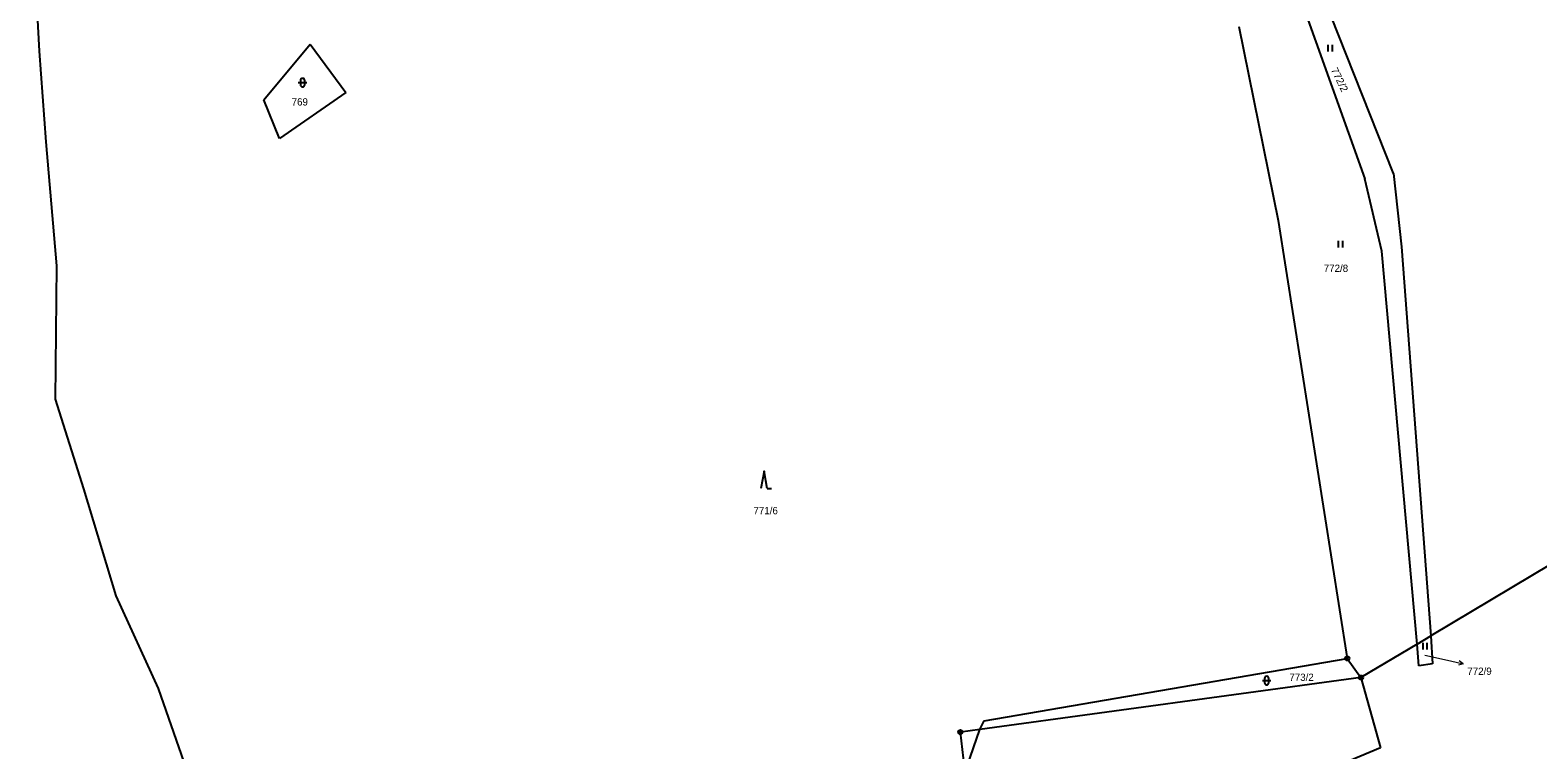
# Model space of a CAD drawing. Extents: x -754970 to -752637, y -970569 to -968179.
# Drawn here: x -754506.1 to -754155, y -970322.9 to -970155.3 of the extents above; entities that cross this region are included whole.
import ezdxf
from ezdxf.enums import TextEntityAlignment as Align

# ---------------------------------------------------------------- set-up
doc = ezdxf.new("R2010")
doc.units = 0
doc.header["$LTSCALE"] = 0.68
for name, color, linetype, lineweight in [('1', 7, 'Continuous', 25), ('3', 7, 'Continuous', 25), ('7', 7, 'Continuous', 13), ('8', 7, 'Continuous', 25)]:
    doc.layers.add(name, color=color, linetype=linetype, lineweight=lineweight)
doc.layers.add('2', color=7, linetype='Continuous')

msp = doc.modelspace()

# ---------------------------------------------------------------- linework, layer by layer
at = {"layer": '1'}
for p, q in [((-754216.79, -970129.79), (-754195.3, -970189.96)), ((-754188.66, -970188.7), (-754212.44, -970128.61)), ((-754224.62, -970154.43), (-754215.47, -970199.68)), ((-754451.69, -970171.53), (-754440.95, -970158.57)), ((-754440.95, -970158.57), (-754432.62, -970169.82)), ((-754502.39, -970181.3), (-754503.93, -970160.19)), ((-754448.06, -970180.57), (-754451.69, -970171.53)), ((-754432.62, -970169.82), (-754448.06, -970180.57)), ((-754499.91, -970210.21), (-754502.39, -970181.3)), ((-754191.35, -970206.76), (-754195.3, -970189.96)), ((-754188.66, -970188.7), (-754186.77, -970205.78)), ((-754215.47, -970199.68), (-754199.39, -970301.65)), ((-754183.14, -970298.3), (-754191.35, -970206.76)), ((-754186.77, -970205.78), (-754179.98, -970296.42)), ((-754500.27, -970241.29), (-754499.91, -970210.21)), ((-754042.77, -970214.3), (-754179.98, -970296.42)), ((-754493.61, -970262.16), (-754500.27, -970241.29)), ((-754486.12, -970287.1), (-754493.61, -970262.16)), ((-754476.28, -970308.62), (-754486.12, -970287.1)), ((-754183.14, -970298.3), (-754196.22, -970306.09)), ((-754183.14, -970298.3), (-754179.98, -970296.42)), ((-754182.71, -970303.39), (-754183.14, -970298.3)), ((-754179.98, -970296.42), (-754179.55, -970302.93)), ((-754283.98, -970316.21), (-754199.39, -970301.65)), ((-754199.39, -970301.65), (-754196.22, -970306.09)), ((-754179.55, -970302.93), (-754182.71, -970303.39)), ((-754468.5, -970330.9), (-754476.28, -970308.62)), ((-754196.22, -970306.09), (-754285, -970318.19)), ((-754196.22, -970306.09), (-754191.69, -970322.5)), ((-754285, -970318.19), (-754283.98, -970316.21)), ((-754285, -970318.19), (-754289.51, -970318.8)), ((-754279.06, -970409.25), (-754289.51, -970318.8)), ((-754287.93, -970326.74), (-754285, -970318.19)), ((-754191.69, -970322.5), (-754258.35, -970350.29))]:
    msp.add_line(p, q, dxfattribs=at)
msp.add_lwpolyline([(-754503.93, -970160.19), (-754504.95, -970141.47), (-754506.14, -970118.68)], dxfattribs=at)
at = {"layer": '3'}
for p, q in [((-754203.851, -970160.26), (-754203.851, -970158.76)), ((-754202.85, -970160.26), (-754202.85, -970158.76)), ((-754443.701, -970167.541), (-754441.699, -970167.541)), ((-754443.201, -970167.041), (-754443.201, -970168.042)), ((-754442.199, -970168.042), (-754442.199, -970167.041)), ((-754201.451, -970205.91), (-754201.451, -970204.41)), ((-754200.45, -970205.91), (-754200.45, -970204.41)), ((-754334.48, -970262.05), (-754333.484, -970262.05)), ((-754181.761, -970299.55), (-754181.761, -970298.05)), ((-754180.76, -970299.55), (-754180.76, -970298.05)), ((-754219.171, -970306.801), (-754217.169, -970306.801)), ((-754218.671, -970306.301), (-754218.671, -970307.302)), ((-754217.669, -970307.302), (-754217.669, -970306.301))]:
    msp.add_line(p, q, dxfattribs=at)
msp.add_lwpolyline([(-754334.48, -970262.05), (-754335.23, -970258.05), (-754335.98, -970262.05)], dxfattribs=at)
for centre, start, end in [((-754442.7, -970167.0409), 0, 180), ((-754442.7, -970168.0409), 180, 359.98789), ((-754218.17, -970306.3009), 0, 180), ((-754218.17, -970307.3009), 180, 359.98789)]:
    msp.add_arc(centre, 0.5, start, end, dxfattribs=at)
at = {"layer": '7'}
msp.add_line((-754172.446, -970302.915), (-754173.309, -970302.202), dxfattribs=at)
msp.add_lwpolyline([(-754181.34, -970300.88), (-754175.37, -970302.24), (-754172.446, -970302.915), (-754173.534, -970303.178)], dxfattribs=at)
at = {"layer": '8'}
for centre, radius in [((-754199.39, -970301.6499), 0.5), ((-754199.39, -970301.6499), 0.0303), ((-754196.22, -970306.0899), 0.5), ((-754196.22, -970306.0899), 0.0303), ((-754289.51, -970318.7999), 0.5), ((-754289.51, -970318.7999), 0.0303)]:
    msp.add_circle(centre, radius, dxfattribs=at)

# ---------------------------------------------------------------- texts
at = {"layer": '2', "width": 1.05}
msp.add_text('772/2', height=1.7, rotation=296, dxfattribs=at).set_placement((-754201.9594, -970167.2254), align=Align.CENTER)
at = {"layer": '2'}
for s, p in [('769', (-754443.349, -970172.865)), ('772/8', (-754202.04, -970211.625)), ('771/6', (-754334.85, -970268.065)), ('773/2', (-754210.05, -970306.885))]:
    msp.add_text(s, height=1.7, dxfattribs=at).set_placement(p, align=Align.CENTER)
msp.add_text('772/9', height=1.7, dxfattribs=at).set_placement((-754171.45, -970305.475))

doc.saveas('drawing.dxf')
